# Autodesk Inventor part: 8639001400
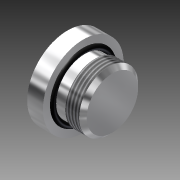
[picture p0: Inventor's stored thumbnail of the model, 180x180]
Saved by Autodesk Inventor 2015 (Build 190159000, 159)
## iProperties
Created: 2013-02
Part Number: 8639001400
Material: Generic
Document SubType Name: Modeling
Designer: Marci
Density: 1 g/cm^3
Appearance: Chrome - Polished
Translation Standard: STEP AP214IS
FileName: 8639001400
PreProcessor: PRO/ENGINEER BY PARAMETRIC TECHNOLOGY CORPORATION, 2006020
PostProcessor: Build: 160, Release: 2012 RTM - Date: Tue 03/01/2011
Sent Units: millimeter
Uncertainty: 0.001
Author: Marci
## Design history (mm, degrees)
node "86390014001"
thread "Thread1" dims "d0" = 10, "d1" = 0
node "8639001400"
node "Base1"
